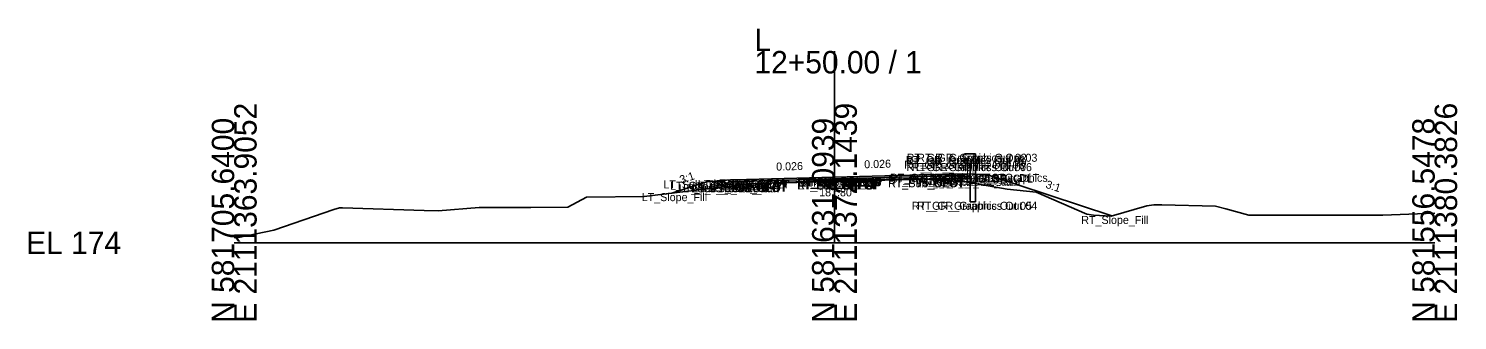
# Model space of a CAD drawing. Extents: x -26 to 3453, y -333 to 9539.
# Drawn here: x -25.7 to 152.8, y 1990.3 to 2026.7 of the extents above; entities that cross this region are included whole.
import ezdxf

# ---------------------------------------------------------------- set-up
doc = ezdxf.new("R2010")
doc.units = 0
for name, color, linetype in [('Default', 7, 'Continuous'), ('Exist Cross Section Cell', 7, 'Continuous'), ('Exist XS Center Line Elevation Label', 7, 'Continuous'), ('Exist XS Ground Line', 7, 'Continuous'), ('Prop CMT Guardrail Graphics', 7, 'Continuous'), ('Prop CMT Pvmt Course 1', 7, 'Continuous'), ('Prop CMT Pvmt Course 2', 7, 'Continuous'), ('Prop CMT Pvmt Course 3', 7, 'Continuous'), ('Prop CMT Pvmt Surface', 7, 'Continuous'), ('Prop CMT Pvmt Surface Shoulder', 7, 'Continuous'), ('Prop CMT Shld Paved Course 1', 7, 'Continuous'), ('Prop CMT Shld Paved Course 2', 7, 'Continuous'), ('Prop CMT Shld Paved Course 3', 7, 'Continuous'), ('Prop CMT Slope Grass', 7, 'Continuous'), ('Prop CMT Subgrade Earthwork', 7, 'Continuous'), ('Prop XS SE Text', 7, 'Continuous'), ('Prop XS Side Slope Text', 7, 'Continuous'), ('Scratch_Level_0', 7, 'Continuous')]:
    doc.layers.add(name, color=color, linetype=linetype)

msp = doc.modelspace()

# ---------------------------------------------------------------- linework, layer by layer
at = {"layer": 'Exist Cross Section Cell'}
for p, q in [((75, 2000), (75, 2023.95)), ((0, 2000), (75, 2000)), ((75, 2000), (150, 2000))]:
    msp.add_line(p, q, dxfattribs=at)
at = {"layer": 'Exist XS Ground Line'}
for p, q in [((51.24, 2005.77), (61.57, 2007.05)), ((61.57, 2007.05), (64.57, 2007.38)), ((64.57, 2007.38), (65.57, 2007.42)), ((65.57, 2007.42), (73.83, 2007.78)), ((73.83, 2007.78), (75, 2007.8)), ((75, 2007.8), (83.61, 2007.98)), ((83.61, 2007.98), (84.39, 2007.97)), ((84.39, 2007.97), (85.61, 2007.98)), ((85.61, 2007.98), (91.14, 2007.66)), ((91.14, 2007.66), (96.59, 2006.71)), ((96.59, 2006.71), (100.2, 2006.31)), ((41.67, 2004.43), (44.01, 2005.7)), ((44.01, 2005.7), (51.24, 2005.77)), ((100.2, 2006.31), (106.53, 2003.57)), ((4.96, 2001.56), (12.45, 2004.15)), ((12.45, 2004.15), (13.17, 2004.37)), ((13.17, 2004.37), (13.53, 2004.36)), ((13.53, 2004.36), (23.72, 2004.03)), ((23.72, 2004.03), (25.47, 2004.01)), ((25.47, 2004.01), (30.61, 2004.39)), ((30.61, 2004.39), (37.06, 2004.42)), ((37.06, 2004.42), (41.67, 2004.43)), ((106.53, 2003.57), (107.38, 2003.47)), ((107.38, 2003.47), (109.57, 2003.32)), ((109.57, 2003.32), (114.04, 2004.62)), ((114.04, 2004.62), (114.89, 2004.74)), ((114.89, 2004.74), (115.91, 2004.74)), ((115.91, 2004.74), (122.63, 2004.58)), ((122.63, 2004.58), (123.91, 2004.25)), ((123.91, 2004.25), (126.79, 2003.43)), ((126.79, 2003.43), (127.24, 2003.43)), ((127.24, 2003.43), (136.09, 2003.45)), ((136.09, 2003.45), (143.53, 2003.46)), ((143.53, 2003.46), (150, 2003.68)), ((0.53, 2000.67), (4.96, 2001.56)), ((0, 2000.65), (0.53, 2000.67))]:
    msp.add_line(p, q, dxfattribs=at)
at = {"layer": 'Prop CMT Guardrail Graphics'}
for points in [[(92.61, 2011.12), (91.28, 2011.12), (91.01, 2010.82)], [(91.01, 2010.82), (91.28, 2010.53)], [(91.28, 2010.53), (91.01, 2010.24)], [(92.61, 2005.12), (92.61, 2011.12)], [(91.01, 2010.24), (91.28, 2009.95), (91.95, 2009.95)], [(91.95, 2009.95), (91.95, 2005.12)], [(91.95, 2005.12), (92.61, 2005.12)]]:
    msp.add_lwpolyline(points, dxfattribs=at)
at = {"layer": 'Prop CMT Pvmt Course 1'}
for points in [[(75, 2008.2), (64, 2007.91)], [(64, 2007.71), (75, 2007.99)], [(64, 2007.91), (64, 2007.71)], [(75, 2008.2), (86, 2008.49)], [(86, 2008.28), (75, 2007.99)], [(75, 2007.99), (75, 2008.2)], [(75, 2007.99), (75, 2008.2)], [(86, 2008.49), (86, 2008.28)]]:
    msp.add_lwpolyline(points, dxfattribs=at)
msp.add_lwpolyline([(75, 2007.99), (75, 2008.08), (75, 2008.08), (75, 2007.99)], close=True, dxfattribs=at)
msp.add_lwpolyline([(75, 2007.99), (75, 2008.08), (75, 2008.08), (75, 2007.99)], close=True, dxfattribs=at)
at = {"layer": 'Prop CMT Pvmt Course 2'}
for points in [[(75, 2007.99), (64, 2007.71)], [(64, 2007.71), (64, 2007.37)], [(64, 2007.37), (75, 2007.66)], [(75, 2007.99), (86, 2008.28)], [(75, 2007.66), (75, 2007.99)], [(75, 2007.66), (75, 2007.99)], [(86, 2007.94), (75, 2007.66)], [(86, 2008.28), (86, 2007.94)]]:
    msp.add_lwpolyline(points, dxfattribs=at)
at = {"layer": 'Prop CMT Pvmt Course 3'}
for points in [[(75, 2007.66), (64, 2007.37)], [(64, 2007.37), (75, 2007.66)], [(64, 2007.37), (64, 2007.37)], [(75, 2007.66), (86, 2007.94)], [(86, 2007.94), (75, 2007.66)], [(75, 2007.66), (75, 2007.66)], [(75, 2007.66), (75, 2007.66)], [(86, 2007.94), (86, 2007.94)]]:
    msp.add_lwpolyline(points, dxfattribs=at)
at = {"layer": 'Prop CMT Pvmt Surface'}
for points in [[(75, 2008.2), (64, 2007.91)], [(75, 2008.2), (86, 2008.49)]]:
    msp.add_lwpolyline(points, dxfattribs=at)
at = {"layer": 'Prop CMT Pvmt Surface Shoulder'}
for points in [[(86, 2008.49), (91, 2008.62)], [(64, 2007.91), (62, 2007.86)]]:
    msp.add_lwpolyline(points, dxfattribs=at)
at = {"layer": 'Prop CMT Shld Paved Course 1'}
for points in [[(86, 2008.49), (91, 2008.62), (91.2, 2008.41)], [(64, 2007.91), (62, 2007.86), (61.79, 2007.65)], [(61.79, 2007.65), (64, 2007.71)], [(64, 2007.71), (64, 2007.91)], [(86, 2008.28), (86, 2008.49)], [(91.2, 2008.41), (86, 2008.28)]]:
    msp.add_lwpolyline(points, dxfattribs=at)
at = {"layer": 'Prop CMT Shld Paved Course 2'}
for points in [[(64, 2007.71), (61.79, 2007.65), (61.44, 2007.31)], [(61.44, 2007.31), (64, 2007.37)], [(64, 2007.37), (64, 2007.71)], [(86, 2008.28), (91.2, 2008.41), (91.53, 2008.09)], [(86, 2007.94), (86, 2008.28)], [(91.53, 2008.09), (86, 2007.94)]]:
    msp.add_lwpolyline(points, dxfattribs=at)
at = {"layer": 'Prop CMT Shld Paved Course 3'}
for points in [[(64, 2007.37), (61.44, 2007.31)], [(61.44, 2007.31), (64, 2007.37)], [(61.44, 2007.31), (61.44, 2007.31), (61.44, 2007.31)], [(64, 2007.37), (64, 2007.37)], [(86, 2007.94), (91.53, 2008.09)], [(91.53, 2008.09), (86, 2007.94)], [(86, 2007.94), (86, 2007.94)], [(91.53, 2008.09), (91.53, 2008.09), (91.53, 2008.09)]]:
    msp.add_lwpolyline(points, dxfattribs=at)
at = {"layer": 'Prop CMT Slope Grass'}
for points in [[(91, 2008.62), (91.01, 2008.62)], [(91.01, 2008.62), (94, 2008.51)], [(94, 2008.51), (109.66, 2003.35)], [(62, 2007.86), (59, 2007.62), (54.68, 2006.2)]]:
    msp.add_lwpolyline(points, dxfattribs=at)
at = {"layer": 'Prop CMT Subgrade Earthwork'}
for points in [[(91.53, 2008.09), (92.02, 2008.58)], [(61.44, 2007.31), (60.97, 2007.78)], [(64, 2007.37), (61.44, 2007.31)], [(75, 2007.66), (64, 2007.37)], [(75, 2007.66), (86, 2007.94)], [(86, 2007.94), (91.53, 2008.09)]]:
    msp.add_lwpolyline(points, dxfattribs=at)

# ---------------------------------------------------------------- texts
at = {"layer": 'Default'}
msp.add_text('-', height=0.0001, dxfattribs=at).set_placement((0, 2000))
at = {"layer": 'Exist Cross Section Cell'}
for s, p in [('L', (65, 2023.95)), ('12+50.00 / 1', (65, 2021.15)), ('EL 174', (-26, 1998.6))]:
    msp.add_text(s, height=2.8, dxfattribs=at).set_placement(p)
for s, p in [('E 2111363.9052', (2.8, 1990)), ('E 2111372.1439', (77.8, 1990)), ('E 2111380.3826', (152.8, 1990)), ('N 581705.6400', (0, 1990)), ('N 581631.0939', (75, 1990)), ('N 581556.5478', (150, 1990))]:
    msp.add_text(s, height=2.8, rotation=90, dxfattribs=at).set_placement(p)
at = {"layer": 'Exist XS Center Line Elevation Label'}
msp.add_text('181.80', height=1, dxfattribs=at).set_placement((73.09, 2005.8))
at = {"layer": 'Prop XS SE Text'}
for p in [(78.73, 2009.3), (67.73, 2009.01)]:
    msp.add_text('0.026', height=1, rotation=1.4894, dxfattribs=at).set_placement(p)
at = {"layer": 'Prop XS Side Slope Text'}
for rotation, p in [(18.2629, (55.85, 2007.37)), (341.7371, (101.31, 2006.89))]:
    msp.add_text('3:1', height=1, rotation=rotation, dxfattribs=at).set_placement(p)
at = {"layer": 'Scratch_Level_0'}
for s, p in [('RT_GR_Graphics Out 08', (83.72, 2009.24)), ('RT_GR_Graphics Out 01', (83.9, 2009.82)), ('RT_GR_Graphics Out 09', (84, 2009.53)), ('RT_GR_Graphics Out 02', (84.02, 2010.12)), ('RT_GR_Graphics Out 03', (85.34, 2010.12)), ('RT_PV1_OEOT', (81.81, 2007.49)), ('RT_GS_OS_GR_Face_Graphics', (81.95, 2007.62)), ('RT_GR_Graphics Out 07', (83.98, 2008.95)), ('RT_Sub_Trench_Out_DLT', (84.61, 2007.58)), ('RT_GR_Graphics Out 06', (84.66, 2008.95)), ('RT_PS1_OEOP', (86.85, 2007.62)), ('RT_GS_OS_CTL', (89.4, 2007.51)), ('LT_Sub_Trench_Out_DLT', (53.62, 2006.78)), ('LT_GS_OS_CTL', (54.46, 2006.62)), ('LT_Sub_Trench_Out', (55.55, 2006.31)), ('LT_PS3_Shelf_Out', (56.1, 2006.31)), ('LT_PS3_OEOP', (57.23, 2006.31)), ('LT_PS2_OEOP', (57.57, 2006.65)), ('LT_PS1_OEOP', (57.91, 2006.86)), ('LT_PV2_OEOT', (59.75, 2006.71)), ('LT_PV3_OEOT', (59.75, 2006.37)), ('LT_Sub_OEOT', (59.77, 2006.37)), ('LT_PV1_OEOT', (59.87, 2006.91)), ('RT_PV2_OEEOP', (70.33, 2006.99)), ('RT_PV3_OEEOP', (70.33, 2006.66)), ('RT_Sub_OEEOP', (70.36, 2006.66)), ('LT_PV2_OEEOP', (70.39, 2006.99)), ('LT_PV3_OEEOP', (70.39, 2006.66)), ('LT_Sub_OEEOP', (70.42, 2006.66)), ('RT_PV1_OEEOP', (70.45, 2007.08)), ('LT_PV1_OEEOP', (70.51, 2007.08)), ('RT_PV2_IEEOP', (70.71, 2006.99)), ('LT_PV2_IEEOP', (70.77, 2006.99)), ('RT_PV1_IEEOP', (70.83, 2007.08)), ('LT_PV1_IEEOP', (70.89, 2007.08)), ('PV2_PGL', (72.35, 2006.99)), ('PV1_PGL', (72.47, 2007.2)), ('RT_PV2_OEOT', (81.69, 2007.28)), ('RT_PV3_OEOT', (81.69, 2006.94)), ('RT_Sub_OEOT', (81.71, 2006.94)), ('RT_Sub_Trench_Out', (85.58, 2007.09)), ('RT_PS3_Shelf_Out', (86.13, 2007.09)), ('RT_PS2_OEOP', (86.93, 2007.41)), ('RT_PS3_OEOP', (87.26, 2007.09)), ('LT_Slope_Fill', (50.92, 2005.2)), ('RT_GR_Graphics Out 05', (84.67, 2004.12)), ('RT_GR_Graphics Out 04', (85.32, 2004.12)), ('RT_Slope_Fill', (105.84, 2002.35))]:
    msp.add_text(s, height=1, dxfattribs=at).set_placement(p)

doc.saveas('drawing.dxf')
